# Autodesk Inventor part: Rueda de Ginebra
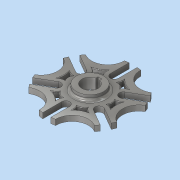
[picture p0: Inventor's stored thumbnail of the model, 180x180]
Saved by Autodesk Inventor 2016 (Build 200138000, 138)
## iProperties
Created: 2015-11
Part Number: Rueda de Ginebra
Material: Steel, Alloy
Document SubType Name: Modeling
Designer: SanPer86
Density: 7.73 g/cm^3
Appearance: Semi-Polished
Mass: 0.121651 g
Surface Area: 0.904011 cm^2
Volume: 0.0157375 cm^3
Author: SanPer86
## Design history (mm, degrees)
sketch "Sketch1"
  geometry: L1 (2.136, 0.8)-(3.636, 1.666); L2 (3, 0)-(0, 0); L3 (0, 0)-(1.624, 0.937); A1 r 0.375 centre (1.949, 1.125) between (1.624, 0.937) and (2.136, 0.8); A2 r 4 centre (0, 0) between (3.778, 1.315) and (3.636, 1.666); A3 r 1.5 centre (4.5, 0) between (3.778, 1.315) and (3, 0)
  constraints: 6 end point, 6 point on circle, 3 centre point, 2 point on line, 1 horizontal, 1 parallel, 1 tangent
  dimensions: "d26" = 1.5 radius of A3; "d27" = 4.5 distance of A3.centre A2.centre; "d28" = 30 deg angle of L2 L3; "d29" = 0.375 radius of A1; "d30" = 2.25 distance of L2.end A1.centre; "d31" = 4 radius of A2
extrude "Extrusion1" new body sketch "Sketch1" distance "d38" = 0.5; taper "d39" = 0 deg
mirror "Mirror1"
pattern_circular "Circular Pattern1" dims angle "d41" = 360 deg
sketch "Sketch2"
  geometry: L1 (-3.449, -1.991)-(0, 0); L2 (0, -3.982)-(0, 0); L3 (3.449, -1.991)-(0, 0); L4 (3.449, 1.991)-(0, 0); L5 (0, 3.982)-(0, 0); L6 (-3.449, 1.991)-(0, 0); C1 r 1.25 at (0, 0); 1 further point
  constraints: 12 end point, 2 coincident, 1 centre point, 19 other
  dimensions: "d43" = 2.5 diameter of C1; "d51" = 360 deg dimension on point (0, 0) L1.start (derived)
extrude "Extrusion2" join sketch "Sketch2" distance "d56" = 0.5; taper "d57" = 0 deg
sketch "Sketch3"
  geometry: C1 r 0.75 at (0, 0); 1 further point
  constraints: 1 centre point, 1 coincident
  dimensions: "d58" = 1.5 diameter of C1
extrude "Extrusion3" cut sketch "Sketch3" distance "d59" = 1; taper "d60" = 0 deg
fillet "Fillet1" dims "d61" = 0.25
sketch "Sketch4"
  geometry: L1 (0.18, 0.728)-(0.18, 0.928); L2 (0.18, 0.928)-(-0.18, 0.928); L3 (-0.18, 0.928)-(-0.18, 0.728); A1 r 0.75 centre (0, 0) between (0.18, 0.728) and (-0.18, 0.728) reference; A2 r 0.75 centre (0, 0) between (0.18, 0.728) and (-0.18, 0.728); 1 further point
  constraints: 6 end point, 4 point on circle, 2 concentric, 2 perpendicular, 1 centre point
  dimensions: "d64" = 0.36 distance of L1.end L2.end; "d65" = 0.2 distance of L1.start L1.end; "d66" = 0.2 distance of L2.end L3.end
extrude "Extrusion4" cut sketch "Sketch4" distance "d67" = 1; taper "d68" = 0 deg
sketch "Sketch5"
  geometry: L1 (0.775, -2.25)-(0.775, -2.377); L2 (1.561, -1.796)-(1.671, -1.86); A1 r 0.775 centre (1.949, -1.125) between (1.288, -1.53) and (1.561, -1.796); A2 r 0.775 centre (0, -2.25) between (0.775, -2.25) and (0.681, -1.88); A3 r 1.965 centre (2.171, -3.76) between (1.671, -1.86) and (0.775, -2.377); A4 r 0.74 centre (0.659, -1.141) between (0.681, -1.88) and (1.288, -1.53); 2 further points
  constraints: 8 point on circle, 4 centre point, 4 end point
extrude "Extrusion5" cut sketch "Sketch5" distance "d73" = 0.6; taper "d74" = 0 deg
fillet "Fillet2" dims "d75" = 0.05
pattern_circular "Circular Pattern2" dims angle "d77" = 360 deg
body "Solid1"
other parameters: "d0" = 19.05 (derived), "d2" = 114.3 (derived), "d4" = 38.1 (derived), "d6" = 38.1 (derived), "d8" = 60 deg (derived), "d10" = 114.3 (derived), "d13" = 114.3 (derived), "d15" = 38.1 (derived), "d17" = 60 deg (derived), "d19" = 114.3 (derived), "d21" = 38.1 (derived), "d23" = 19.05 (derived), "d71" = 0.4
